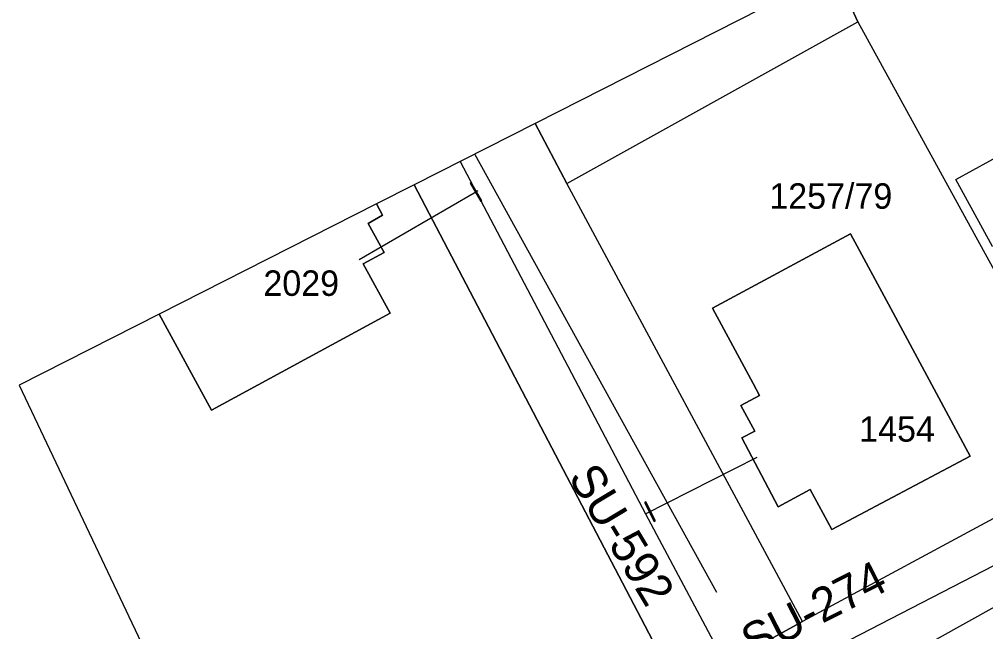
# Model space of a CAD drawing. Extents: x -562248 to -562040, y -1079385 to -1079027.
# Drawn here: x -562247.9 to -562191, y -1079326.6 to -1079290.5 of the extents above; entities that cross this region are included whole.
import ezdxf

# ---------------------------------------------------------------- set-up
doc = ezdxf.new("R2010")
doc.units = 0
for name, color, linetype in [('Armatura - popis', 7, 'Continuous'), ('Armatura vodovodní', 7, 'Continuous'), ('Kanalizační stoka', 7, 'Continuous'), ('Parcela-polygon', 7, 'Continuous'), ('Parcela-text', 7, 'Continuous'), ('Vodovodní přípojka', 7, 'Continuous'), ('Vodovodní řad', 7, 'Continuous')]:
    doc.layers.add(name, color=color, linetype=linetype)

msp = doc.modelspace()

# ---------------------------------------------------------------- linework, layer by layer
at = {"layer": 'Armatura vodovodní'}
for points in [[(-562220.719, -1079301.219), (-562220.651, -1079301.18), (-562221.281, -1079300.1), (-562221.348, -1079300.139)], [(-562210.49, -1079320.094), (-562210.421, -1079320.059), (-562210.988, -1079318.945), (-562211.057, -1079318.98)]]:
    msp.add_lwpolyline(points, close=True, dxfattribs=at)
at = {"layer": 'Kanalizační stoka'}
for points in [[(-562138.86, -1079296.41), (-562202.88, -1079332.07)], [(-562206.81, -1079324.29), (-562221.076, -1079298.424)]]:
    msp.add_lwpolyline(points, dxfattribs=at)
at = {"layer": 'Parcela-polygon'}
for p, q in [((-562199.855, -1079287.648), (-562217.511, -1079296.614)), ((-562217.511, -1079296.614), (-562224.636, -1079300.232)), ((-562224.636, -1079300.232), (-562226.87, -1079301.366)), ((-562226.87, -1079301.366), (-562239.675, -1079307.869))]:
    msp.add_line(p, q, dxfattribs=at)
for points in [[(-562050.734, -1079242.89), (-562074.7, -1079253.09), (-562082.29, -1079260.79), (-562083.07, -1079261.58), (-562094.62, -1079267.87), (-562113.94, -1079278.46), (-562131.57, -1079288.07), (-562135.96, -1079290.46), (-562143.99, -1079294.84), (-562166.66, -1079307.21), (-562184.27, -1079316.57), (-562201.76, -1079326), (-562209.06, -1079330.03), (-562233.192, -1079343.166)], [(-562199.855, -1079287.648), (-562198.5, -1079290.62), (-562184.27, -1079316.57), (-562166.66, -1079307.21), (-562182.089, -1079278.626)], [(-562217.511, -1079296.614), (-562215.64, -1079300.17), (-562198.5, -1079290.62), (-562199.855, -1079287.648)], [(-562224.636, -1079300.232), (-562209.06, -1079330.03), (-562201.76, -1079326), (-562215.64, -1079300.17), (-562217.511, -1079296.614)], [(-562190.55, -1079303.87), (-562192.71, -1079299.92), (-562187.71, -1079297.18), (-562185.55, -1079301.13), (-562190.55, -1079303.87)], [(-562233.192, -1079343.166), (-562209.06, -1079330.03), (-562224.636, -1079300.232)], [(-562226.87, -1079301.366), (-562226.51, -1079302.03), (-562227.36, -1079302.53), (-562226.42, -1079304.24), (-562227.64, -1079304.9), (-562226.05, -1079307.81), (-562236.58, -1079313.54), (-562239.675, -1079307.869)], [(-562239.675, -1079307.869), (-562236.58, -1079313.54), (-562226.05, -1079307.81), (-562227.64, -1079304.9), (-562226.42, -1079304.24), (-562227.36, -1079302.53), (-562226.51, -1079302.03), (-562226.87, -1079301.366)], [(-562239.675, -1079307.869), (-562247.917, -1079312.054), (-562233.192, -1079343.166)]]:
    msp.add_lwpolyline(points, dxfattribs=at)
for points in [[(-562198.5, -1079290.62), (-562184.27, -1079316.57), (-562201.76, -1079326), (-562215.64, -1079300.17)], [(-562187.71, -1079297.18), (-562185.55, -1079301.13), (-562190.55, -1079303.87), (-562192.71, -1079299.92)], [(-562205.39, -1079313.26), (-562204.29, -1079312.67), (-562204.67, -1079311.96), (-562207.06, -1079307.52), (-562198.93, -1079303.14), (-562196.55, -1079307.54), (-562191.87, -1079316.25), (-562200.03, -1079320.58), (-562201.3, -1079318.22), (-562203.19, -1079319.24), (-562205.32, -1079315.17), (-562204.57, -1079314.77)], [(-562201.3, -1079318.22), (-562200.03, -1079320.58), (-562191.87, -1079316.25), (-562196.55, -1079307.54), (-562198.93, -1079303.14), (-562207.06, -1079307.52), (-562204.67, -1079311.96), (-562204.29, -1079312.67), (-562205.39, -1079313.26), (-562204.57, -1079314.77), (-562205.32, -1079315.17), (-562203.19, -1079319.24)]]:
    msp.add_lwpolyline(points, close=True, dxfattribs=at)
at = {"layer": 'Vodovodní přípojka'}
for points in [[(-562220.882, -1079300.591), (-562221.109, -1079300.723), (-562227.879, -1079304.673)], [(-562211.001, -1079319.653), (-562204.42, -1079316.302)]]:
    msp.add_lwpolyline(points, dxfattribs=at)
at = {"layer": 'Vodovodní řad'}
for points in [[(-562205.614, -1079330.519), (-562174.097, -1079314.233), (-562147.992, -1079299.695), (-562146.568, -1079298.894), (-562118.26, -1079283.525), (-562104.098, -1079276.026), (-562101.887, -1079274.855), (-562091.855, -1079269.457), (-562077.721, -1079261.793), (-562076.873, -1079261.222)], [(-562221.926, -1079298.856), (-562211.001, -1079319.653), (-562205.879, -1079329.29)]]:
    msp.add_lwpolyline(points, dxfattribs=at)

# ---------------------------------------------------------------- texts
at = {"layer": 'Armatura - popis'}
for s, rotation, p in [('SU-592', 301.0546, (-562215.597, -1079317.493)), ('SU-274', 27.0414, (-562204.692, -1079328.232))]:
    msp.add_text(s, height=2, rotation=rotation, dxfattribs=at).set_placement(p)
at = {"layer": 'Parcela-text'}
for s, p in [('1257/79', (-562203.71, -1079301.65)), ('2029', (-562233.53, -1079306.79)), ('1454', (-562198.41, -1079315.39))]:
    msp.add_text(s, height=1.5, dxfattribs=at).set_placement(p)

doc.saveas('drawing.dxf')
